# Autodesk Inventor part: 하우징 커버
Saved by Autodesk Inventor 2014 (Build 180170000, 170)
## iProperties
Created: 2026-05
Part Number: 하우징 커버
Material: 일반
Document SubType Name: Modeling
Designer: dg
Density: 1 g/cm^3
Appearance: 기본값
Author: dg
Author: jhkim
Creation Date: 2026-04-23
Sending System: Autodesk Inventor 2027
Preprocessor: ST-DEVELOPER v20.1
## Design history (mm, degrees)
node "하우징 커버1"
node "솔리드1"
node "기준1"
